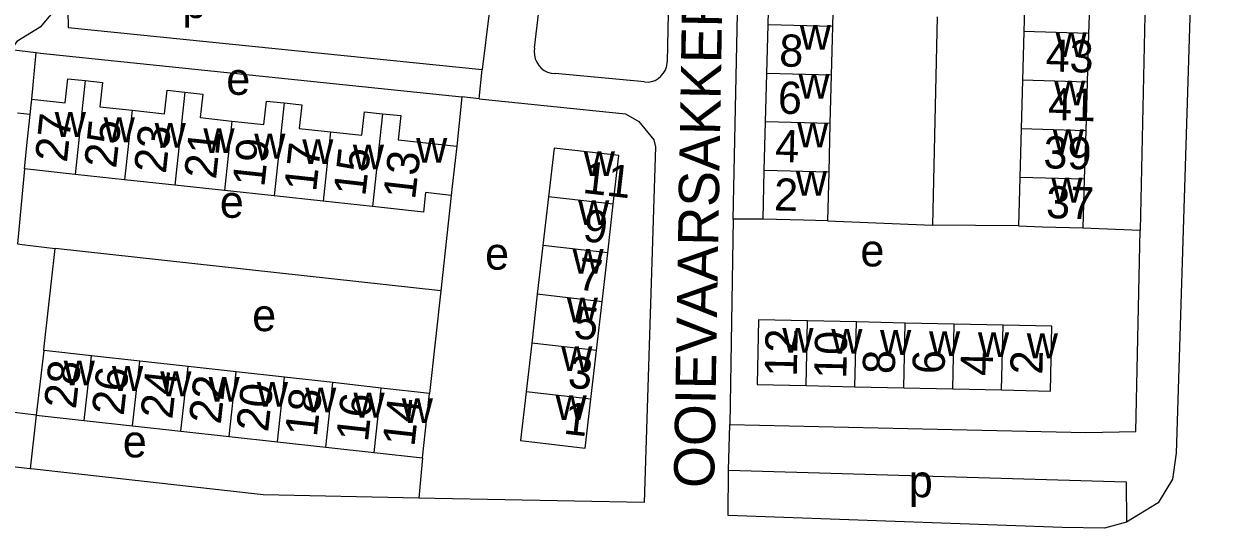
# Model space of a CAD drawing. Extents: x 161936 to 163647, y 386450 to 388633.
# Drawn here: x 162746.8 to 162894.3, y 387767.8 to 387830.5 of the extents above; entities that cross this region are included whole.
import ezdxf

# ---------------------------------------------------------------- set-up
doc = ezdxf.new("R2010")
doc.units = 0
for name, color, linetype in [('BLT_Basislijn', 7, 'Continuous'), ('BLT_Bebouwing', 7, 'Continuous'), ('BLT_Centroide', 7, 'Continuous'), ('BLT_Huisnummer', 7, 'Continuous'), ('BLT_Huisnummer_ tussenligend', 7, 'Continuous'), ('BLT_Onderverdeling_panden', 7, 'Continuous'), ('BLT_Straatnaam', 7, 'Continuous')]:
    doc.layers.add(name, color=color, linetype=linetype)

msp = doc.modelspace()

# ---------------------------------------------------------------- linework, layer by layer
at = {"layer": 'BLT_Basislijn'}
for p, q in [((162834.96, 387806.17), (162836.3, 387872.09)), ((162810.27, 387827.47), (162814.44, 387862.76)), ((162827.61, 387861.84), (162826.75, 387825.73)), ((162804.64, 387831.81), (162803.77, 387824.77)), ((162860.3, 387831.3), (162859.73, 387805.46)), ((162745.3, 387827.27), (162748.39, 387826.89)), ((162747.87, 387821.1), (162748.39, 387826.89)), ((162803.42, 387821.14), (162803.77, 387824.77)), ((162823.94, 387823.23), (162812.86, 387824.27)), ((162801.27, 387821.37), (162800.64, 387815.24)), ((162803.42, 387821.14), (162801.27, 387821.37)), ((162747.66, 387819.19), (162746.09, 387819.37)), ((162746.93, 387812.43), (162746.05, 387803.12)), ((162799.94, 387809.14), (162798.64, 387797.27)), ((162834.96, 387806.17), (162834.55, 387780.7)), ((162838.67, 387806.18), (162834.96, 387806.17)), ((162846.67, 387805.98), (162859.73, 387805.46)), ((162870.38, 387805.34), (162859.73, 387805.46)), ((162878.37, 387805.1), (162885.52, 387804.83)), ((162798.64, 387797.27), (162750.75, 387802.54)), ((162798.64, 387797.27), (162797.24, 387784.53)), ((162748.37, 387781.83), (162745.66, 387782.17)), ((162748.37, 387781.83), (162747.65, 387775.18)), ((162834.38, 387775.02), (162834.55, 387780.7)), ((162796.35, 387776.55), (162795.9, 387771.53))]:
    msp.add_line(p, q, dxfattribs=at)
for points in [[(162887.96, 387921.99), (162891.62, 387921.25), (162893.52, 387919.28), (162894.33, 387917.11), (162894.26, 387914.42), (162889.96, 387777.13), (162889.5, 387773.9), (162887.73, 387770.97), (162883.82, 387768.54)], [(162886.87, 387868.7), (162886.85, 387867.71), (162885.52, 387804.83)], [(162752.33, 387832.07), (162750.65, 387832.14), (162748.9, 387830.04), (162746, 387828.24), (162745.3, 387827.27)], [(162752.33, 387832.07), (162752.37, 387830.01), (162803.77, 387824.77)], [(162810.27, 387827.47), (162810.22, 387827), (162810.26, 387826.54), (162810.37, 387826.09), (162810.55, 387825.67), (162810.81, 387825.28), (162811.12, 387824.95), (162811.49, 387824.67), (162811.91, 387824.46), (162812.35, 387824.32), (162812.86, 387824.27)], [(162748.39, 387826.89), (162748.93, 387826.82), (162801.27, 387821.37)], [(162823.94, 387823.23), (162824.39, 387823.22), (162824.83, 387823.29), (162825.25, 387823.43), (162825.65, 387823.65), (162825.99, 387823.93), (162826.28, 387824.27), (162826.51, 387824.65), (162826.66, 387825.07), (162826.74, 387825.51), (162826.75, 387825.73)], [(162803.42, 387821.14), (162821.58, 387819.28), (162823.24, 387818.32), (162825.09, 387816.03), (162825.29, 387815.17), (162823.91, 387770.98), (162797.93, 387771.48), (162795.9, 387771.53)], [(162834.55, 387780.7), (162878.76, 387779.68), (162884.98, 387779.82), (162885.52, 387804.83)], [(162746.05, 387803.12), (162746.66, 387803.06), (162750.75, 387802.54)], [(162749.33, 387789.89), (162749.39, 387790.36), (162750.75, 387802.54)], [(162747.65, 387775.18), (162674.66, 387783.49), (162673.23, 387783.65)], [(162795.9, 387771.53), (162776.6, 387771.93), (162747.77, 387775.16), (162747.65, 387775.18)], [(162883.82, 387768.54), (162881.06, 387767.8), (162875.83, 387767.88), (162834.35, 387769.36), (162834.38, 387775.02)], [(162834.38, 387775.02), (162883.77, 387773.55), (162883.82, 387768.54)]]:
    msp.add_lwpolyline(points, dxfattribs=at)
at = {"layer": 'BLT_Bebouwing'}
for p, q in [((162839.29, 387830.33), (162839.45, 387836.36)), ((162847.45, 387836.16), (162847.29, 387830.12)), ((162871.24, 387835.53), (162871.07, 387829.49)), ((162879.29, 387835.29), (162879.1, 387829.25)), ((162839.14, 387824.29), (162839.29, 387830.33)), ((162847.29, 387830.12), (162847.14, 387824.09)), ((162871.07, 387829.49), (162870.9, 387823.46)), ((162879.1, 387829.25), (162878.92, 387823.21)), ((162838.98, 387818.26), (162839.14, 387824.29)), ((162847.14, 387824.09), (162846.98, 387818.05)), ((162870.9, 387823.46), (162870.73, 387817.42)), ((162878.92, 387823.21), (162878.74, 387817.17)), ((162747.66, 387819.19), (162747.87, 387821.1)), ((162838.82, 387812.22), (162838.98, 387818.26)), ((162846.98, 387818.05), (162846.82, 387812.01)), ((162870.73, 387817.42), (162870.56, 387811.38)), ((162878.74, 387817.17), (162878.55, 387811.14)), ((162753.22, 387811.75), (162746.93, 387812.43)), ((162759.37, 387811.09), (162753.22, 387811.75)), ((162838.67, 387806.18), (162838.82, 387812.22)), ((162846.82, 387812.01), (162846.67, 387805.98)), ((162870.56, 387811.38), (162870.38, 387805.34)), ((162765.61, 387810.41), (162759.37, 387811.09)), ((162771.78, 387809.74), (162765.61, 387810.41)), ((162777.93, 387809.08), (162771.78, 387809.74)), ((162878.55, 387811.14), (162878.37, 387805.1)), ((162784.02, 387808.42), (162777.93, 387809.08)), ((162790.17, 387807.75), (162784.02, 387808.42)), ((162812.03, 387808.97), (162811.33, 387802.91)), ((162819.37, 387801.99), (162820.06, 387808.05)), ((162811.33, 387802.91), (162810.63, 387796.86)), ((162818.67, 387795.93), (162819.37, 387801.99)), ((162810.63, 387796.86), (162809.93, 387790.8)), ((162817.97, 387789.87), (162818.67, 387795.93)), ((162850.26, 387793.42), (162844.19, 387793.56)), ((162856.33, 387793.29), (162850.26, 387793.42)), ((162862.41, 387793.15), (162856.33, 387793.29)), ((162868.48, 387793.02), (162862.41, 387793.15)), ((162809.93, 387790.8), (162809.23, 387784.74)), ((162755.25, 387789.23), (162749.33, 387789.89)), ((162761.25, 387788.56), (162755.25, 387789.23)), ((162817.27, 387783.81), (162817.97, 387789.87)), ((162767.25, 387787.89), (162761.25, 387788.56)), ((162773.24, 387787.22), (162767.25, 387787.89)), ((162779.24, 387786.55), (162773.24, 387787.22)), ((162785.24, 387785.88), (162779.24, 387786.55)), ((162791.23, 387785.2), (162785.24, 387785.88)), ((162797.24, 387784.53), (162791.23, 387785.2)), ((162844.01, 387785.51), (162850.08, 387785.38)), ((162850.08, 387785.38), (162856.15, 387785.24)), ((162856.15, 387785.24), (162862.23, 387785.11)), ((162862.23, 387785.11), (162868.3, 387784.97)), ((162748.37, 387781.83), (162754.37, 387781.17)), ((162754.37, 387781.17), (162760.36, 387780.51)), ((162760.36, 387780.51), (162766.36, 387779.85)), ((162766.36, 387779.85), (162772.36, 387779.19)), ((162772.36, 387779.19), (162778.36, 387778.53)), ((162778.36, 387778.53), (162784.36, 387777.87)), ((162784.36, 387777.87), (162790.35, 387777.21)), ((162790.35, 387777.21), (162796.35, 387776.55))]:
    msp.add_line(p, q, dxfattribs=at)
for points in [[(162747.87, 387821.1), (162752.01, 387820.65), (162752.34, 387823.62), (162754.48, 387823.39)], [(162754.48, 387823.39), (162756.62, 387823.15), (162756.29, 387820.16), (162760.31, 387819.73)], [(162760.31, 387819.73), (162764.32, 387819.29), (162764.64, 387822.19), (162766.85, 387821.95)], [(162766.85, 387821.95), (162769.07, 387821.71), (162768.76, 387818.81), (162772.71, 387818.38)], [(162772.71, 387818.38), (162776.67, 387817.95), (162776.98, 387820.86), (162779.18, 387820.62)], [(162779.18, 387820.62), (162781.38, 387820.38), (162781.06, 387817.45), (162784.96, 387817.03)], [(162746.93, 387812.43), (162747.33, 387816.13), (162747.66, 387819.19)], [(162784.96, 387817.03), (162788.85, 387816.61), (162789.16, 387819.53), (162791.41, 387819.29)], [(162791.41, 387819.29), (162793.66, 387819.05), (162793.34, 387816.04), (162800.64, 387815.24)], [(162800.64, 387815.24), (162800.07, 387810.3), (162799.94, 387809.14)], [(162820.06, 387808.05), (162820.76, 387814.1), (162812.72, 387815.02), (162812.03, 387808.97)], [(162799.94, 387809.14), (162796.76, 387809.51), (162796.5, 387807.06), (162790.17, 387807.75)], [(162846.67, 387805.98), (162843.67, 387806.05), (162838.67, 387806.18)], [(162870.38, 387805.34), (162873.37, 387805.25), (162878.37, 387805.1)], [(162844.19, 387793.56), (162838.12, 387793.69), (162837.94, 387785.65), (162844.01, 387785.51)], [(162868.3, 387784.97), (162874.37, 387784.84), (162874.55, 387792.88), (162868.48, 387793.02)], [(162749.33, 387789.89), (162748.37, 387781.83)], [(162809.23, 387784.74), (162808.54, 387778.68), (162816.57, 387777.76), (162817.27, 387783.81)], [(162796.35, 387776.55), (162796.9, 387781.52), (162797.24, 387784.53)]]:
    msp.add_lwpolyline(points, dxfattribs=at)
at = {"layer": 'BLT_Onderverdeling_panden'}
for p, q in [((162847.29, 387830.12), (162839.29, 387830.33)), ((162879.1, 387829.25), (162871.07, 387829.49)), ((162754.48, 387823.39), (162753.22, 387811.75)), ((162847.14, 387824.09), (162839.14, 387824.29)), ((162878.92, 387823.21), (162870.9, 387823.46)), ((162766.85, 387821.95), (162765.61, 387810.41)), ((162779.18, 387820.62), (162777.93, 387809.08)), ((162760.31, 387819.73), (162759.37, 387811.09)), ((162791.41, 387819.29), (162790.17, 387807.75)), ((162772.71, 387818.38), (162771.78, 387809.74)), ((162846.98, 387818.05), (162838.98, 387818.26)), ((162878.74, 387817.17), (162870.73, 387817.42)), ((162784.96, 387817.03), (162784.02, 387808.42)), ((162846.82, 387812.01), (162838.82, 387812.22)), ((162878.55, 387811.14), (162870.56, 387811.38)), ((162820.06, 387808.05), (162812.03, 387808.97)), ((162819.37, 387801.99), (162811.33, 387802.91)), ((162818.67, 387795.93), (162810.63, 387796.86)), ((162844.01, 387785.51), (162844.19, 387793.56)), ((162850.08, 387785.38), (162850.26, 387793.42)), ((162856.15, 387785.24), (162856.33, 387793.29)), ((162862.23, 387785.11), (162862.41, 387793.15)), ((162868.3, 387784.97), (162868.48, 387793.02)), ((162817.97, 387789.87), (162809.93, 387790.8)), ((162754.37, 387781.17), (162755.25, 387789.23)), ((162760.36, 387780.51), (162761.25, 387788.56)), ((162766.36, 387779.85), (162767.25, 387787.89)), ((162772.36, 387779.19), (162773.24, 387787.22)), ((162778.36, 387778.53), (162779.24, 387786.55)), ((162784.36, 387777.87), (162785.24, 387785.88)), ((162790.35, 387777.21), (162791.23, 387785.2)), ((162817.27, 387783.81), (162809.23, 387784.74))]:
    msp.add_line(p, q, dxfattribs=at)

# ---------------------------------------------------------------- texts
at = {"layer": 'BLT_Centroide'}
for s, p in [('p', (162766.54, 387831.17)), ('w', (162843.22, 387827.22)), ('w', (162875, 387826.34)), ('e', (162772, 387821.63)), ('w', (162843.06, 387821.16)), ('w', (162874.82, 387820.31)), ('w', (162750.7, 387816.41)), ('w', (162756.77, 387815.75)), ('w', (162763.11, 387815.06)), ('w', (162769.16, 387814.39)), ('w', (162842.91, 387815.12)), ('w', (162874.64, 387814.28)), ('w', (162775.48, 387813.72)), ('w', (162781.44, 387813.05)), ('w', (162795.58, 387813.19)), ('w', (162787.72, 387812.36)), ('w', (162816.4, 387811.53)), ('w', (162842.74, 387809.09)), ('w', (162874.47, 387808.25)), ('e', (162771.2, 387806.36)), ('w', (162815.7, 387805.47)), ('e', (162804.15, 387799.92)), ('w', (162815, 387799.41)), ('e', (162850.76, 387800.32)), ('w', (162814.3, 387793.38)), ('e', (162775.22, 387792.28)), ('w', (162841.06, 387789.59)), ('w', (162847.14, 387789.47)), ('w', (162853.2, 387789.33)), ('w', (162859.28, 387789.19)), ('w', (162865.36, 387789.06)), ('w', (162871.42, 387788.92)), ('w', (162813.6, 387787.31)), ('w', (162751.81, 387785.53)), ('w', (162757.81, 387784.86)), ('w', (162763.8, 387784.2)), ('w', (162769.8, 387783.53)), ('w', (162775.8, 387782.88)), ('w', (162781.8, 387782.2)), ('w', (162787.8, 387781.55)), ('w', (162793.8, 387780.86)), ('w', (162812.9, 387781.25)), ('e', (162759.15, 387776.6)), ('p', (162856.77, 387771.65))]:
    msp.add_text(s, height=4, dxfattribs=at).set_placement(p)
at = {"layer": 'BLT_Huisnummer'}
for s, rotation, p in [('6', 358.5106, (162840.47, 387819.3)), ('41', 358.2621, (162874.01, 387818.52)), ('27', 83.8185, (162752.2, 387813.15)), ('21', 83.8229, (162770.72, 387811.07)), ('17', 83.8169, (162783.15, 387809.51)), ('13', 83.4159, (162795.44, 387808.53)), ('11', 353.4275, (162816.16, 387809.46)), ('2', 358.5103, (162839.99, 387807.28)), ('37', 358.2577, (162873.78, 387806.33)), ('5', 353.4283, (162815.03, 387791.44)), ('12', 88.7184, (162842.85, 387786.59)), ('6', 88.7181, (162861.21, 387786.91)), ('2', 88.7255, (162873.36, 387786.86)), ('28', 83.7192, (162753.31, 387782.52)), ('22', 83.724, (162771.31, 387780.63)), ('18', 83.7211, (162783.24, 387779.06)), ('14', 83.651, (162795.36, 387777.85)), ('1', 353.4283, (162813.78, 387779.56))]:
    msp.add_text(s, height=4, rotation=rotation, dxfattribs=at).set_placement(p)
at = {"layer": 'BLT_Huisnummer_ tussenligend'}
for s, rotation, p in [('8', 358.5106, (162840.64, 387825.16)), ('43', 358.2621, (162873.72, 387824.55)), ('25', 83.8229, (162758.31, 387812.41)), ('23', 83.8229, (162764.49, 387811.76)), ('4', 358.5103, (162840.14, 387813.3)), ('19', 83.8169, (162776.72, 387810.09)), ('39', 358.2577, (162873.45, 387812.52)), ('15', 83.4159, (162789.26, 387808.94)), ('9', 353.4283, (162816.17, 387803.48)), ('7', 353.4283, (162815.51, 387797.46)), ('10', 88.7181, (162849, 387786.32)), ('3', 353.4283, (162814.31, 387785.31)), ('8', 88.7181, (162855.03, 387786.92)), ('4', 88.7255, (162867.18, 387786.68)), ('26', 83.7192, (162759.25, 387781.7)), ('24', 83.724, (162765.29, 387781.27)), ('20', 83.7211, (162777.19, 387779.66)), ('16', 83.651, (162789.59, 387778.43))]:
    msp.add_text(s, height=4, rotation=rotation, dxfattribs=at).set_placement(p)
at = {"layer": 'BLT_Straatnaam'}
msp.add_text('OOIEVAARSAKKER', height=4.9999, rotation=89.0278, dxfattribs=at).set_placement((162832.58, 387772.76))

doc.saveas('drawing.dxf')
